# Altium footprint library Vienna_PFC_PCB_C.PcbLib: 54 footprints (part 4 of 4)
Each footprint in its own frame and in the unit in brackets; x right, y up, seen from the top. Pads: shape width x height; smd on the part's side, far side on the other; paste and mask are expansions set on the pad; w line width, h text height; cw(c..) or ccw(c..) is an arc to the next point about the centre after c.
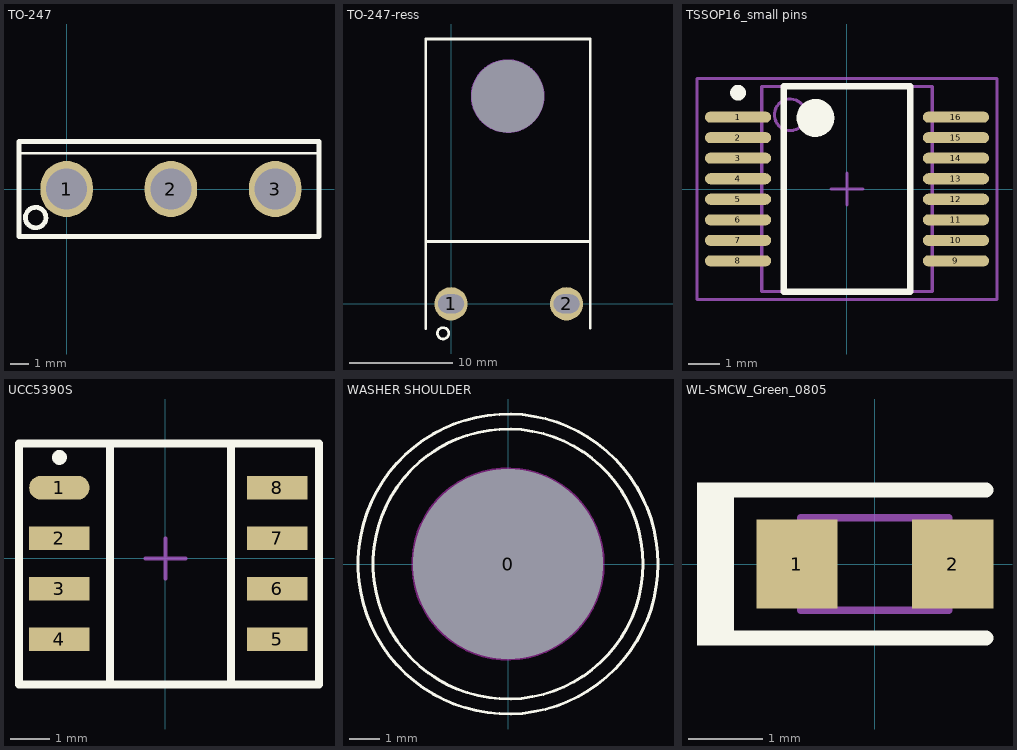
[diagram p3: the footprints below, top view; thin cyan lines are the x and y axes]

## TO-247 [mm]
pads (3):
  oval 2.8x3 hole 2.2: 1(0,0) 2(5.563,0) 3(11.125,0)
Top Overlay:
  lines w0.152: -2.413,1.905 13.335,1.905
  lines w0.254: -2.159,-1.321 ccw(c-1.651,-1.524) -2.106,-1.221 ; -2.54,-2.54 13.462,-2.54 13.462,2.54 -2.54,2.54 -2.54,-2.54
3D body "User Library-TO-247.STEP": height 20.33, standoff -15.73, extent -2.159,-2.667 13.081,1.905

## TO-247-ress [mm]
pads (3):
  round 0 hole 7: 0(5.45,20)
  round 3.2 hole 1.8 slot 2.5 at 0 deg: 1(0,0) 2(11.125,0)
Top Overlay:
  lines w0.254: -2.44,-2.388 -2.44,6.014 -2.44,25.5 13.411,25.5 13.4,25.489 13.4,6.085 13.4,2.743 13.4,-2.338 ; -2.337,5.994 13.31,5.994 ; -1.272,-2.64 ccw(c-0.764,-2.843) -1.219,-2.54
Mechanical 1:
  circle w0.254: c5.45,20 r3.423
3D body "Diode.STEP": height 5.26, standoff -9.24, extent -2.489,-0.504 13.411,25.396

## TSSOP16_small pins [mm] "SOP, 16-Leads, Body 6.2x5.3mm, Pitch 0.65mm, IPC Medium Density"
height 2
pads (16):
  oval 2.1x0.35 smd: 1(-3.45,2.275) 2(-3.45,1.625) 3(-3.45,0.975) 4(-3.45,0.325) 5(-3.45,-0.325) 6(-3.45,-0.975) 7(-3.45,-1.625) 8(-3.45,-2.275) 9(3.45,-2.275) 10(3.45,-1.625) 11(3.45,-0.975) 12(3.45,-0.325) 13(3.45,0.325) 14(3.45,0.975) 15(3.45,1.625) 16(3.45,2.275)
Top Overlay:
  circle w0.25: c-3.45,3.05 r0.125
  circle w0.6: c-1,2.25 r0.3
  lines w0.2: -2,-3.25 -2,3.25 2,3.25 2,-3.25 -2,-3.25
Mechanical 13:
  circle w0.1: c-1.8,2.35 r0.5
  lines w0.1: -2.7,-3.25 -2.7,3.25 2.7,3.25 2.7,-3.25 -2.7,-3.25
Mechanical 15:
  lines w0.1: -0.5,0 0.5,0 ; 0,-0.5 0,0.5 ; -4.75,-3.5 -4.75,3.5 4.75,3.5 4.75,-3.5 -4.75,-3.5
3D body: height 2, standoff 0, extent -2.7,-3.25 2.7,3.25

## UCC5390S [mm] "SOIC, 8-Leads, Body 5.95x7.6mm (max), Pitch 1.27mm"
height 2.8
pads (8):
  oval 1.52x0.6 smd: 1(-2.667,1.778)
  rect 1.52x0.6 smd: 2(-2.667,0.508) 3(-2.667,-0.762) 4(-2.667,-2.032) 5(2.813,-2.032) 6(2.813,-0.762) 7(2.813,0.508) 8(2.813,1.778)
Top Overlay:
  circle w0.3: c-2.667,2.54 r0.036
  lines w0.2: -3.683,-3.175 -3.683,2.896 3.861,2.896 3.861,-3.175 -3.683,-3.175 ; -1.4,-3.175 -1.4,2.896 1.651,2.896 1.651,-3.175 -1.4,-3.175
Mechanical 13:
  lines w0.1: -1.4,-3.175 -1.4,2.896 1.651,2.896 1.651,-3.175 -1.4,-3.175
Mechanical 15:
  lines w0.1: -0.5,0 0.5,0 ; 0,-0.5 0,0.5
3D body: height 1.7, standoff 0, extent -1.4,-3.048 1.651,2.794

## WASHER SHOULDER [mm] "WASHER SHOULDER"
height 1
pads (1):
  round 4.35 hole 6.35: 0(0,0)
Top Overlay:
  circle w0.1: c0,0 r5
  circle w0.1: c0,0 r4.5
Keep-Out Layer:
  circle w0.1: c0,0 r3.175
3D body "M4_Screws.STEP": height 3.58, standoff -14.92, extent -4.504,-4.504 4.496,4.496

## WL-SMCW_Green_0805 [mm] "SMD, 2-Leads, Body 2x1.25mm"
height 0.8
pads (2):
  rect 1.1x1.2 smd: 1(-1.05,0) 2(1.05,0)
Top Overlay:
  rectangle: -2.4,-1.1 -2,1.1
  lines w0.2: 1.5,-1 -2,-1 -2,1 1.5,1
Mechanical 5:
  lines w0.1: -1,-0.625 1,-0.625 1,-0.2 cw(c1,0) 1,0.2 1,0.625 -1,0.625 -1,0.425 -1,0.35 -1,0.2 cw(c-1,0) -1,-0.2 -1,-0.35 -1,-0.425 -1,-0.625
3D body "WL-SMCW_0805.stp": height 0.7, standoff 0, extent -1,-0.625 1,0.625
